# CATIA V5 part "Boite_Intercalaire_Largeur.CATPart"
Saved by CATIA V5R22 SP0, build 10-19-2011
Part number: Boite_Intercalaire_Largeur
Bounding box of the stored display mesh (mm): x -2.5 to 2.5, y -59.5 to 59.5, z -15 to 15
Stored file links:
  U:\S9A\PER\CAO\Assemblage\Reservoir_Boite\Boite\Boite_Intercalaire_Largeur.CATPart
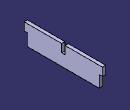
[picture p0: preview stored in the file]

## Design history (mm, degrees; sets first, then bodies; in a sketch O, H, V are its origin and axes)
Body1 (main body)
  Sketch1 on yz-plane, origin (0, 0, 0), H (0, 1, 0), V (0, 0, 1)
    line L1 (-59.5, 15) -> (59.5, 15)
    line L2 (59.5, 15) -> (59.5, -15)
    line L3 (59.5, -15) -> (-59.5, -15)
    line L4 (-59.5, -15) -> (-59.5, 15)
    distance L2 L4 = 119
    distance L1 L3 = 30
    horizontal: L1 H, L3 H
    vertical: L2 V, L4 V
    symmetry: L2 L4 V, L3 L1 H
  Pad1: profile Sketch1, direction (1, 0, 0), length 2.5, mirrored extent
  Sketch2 on yz-plane, origin (0, 0, 0), H (0, 1, 0), V (0, 0, 1)
    line L1 (-2.5, 15) -> (2.5, 15)
    line L2 (2.5, 15) -> (2.5, 3)
    line L3 (2.5, 3) -> (-2.5, 3)
    line L4 (-2.5, 3) -> (-2.5, 15)
    reference projected line E1 (59.5, 15) -> (-59.5, 15) from edge [face of Pad1 from Sketch1.L1 | end face of Pad1]
    distance L2 L4 = 5
    distance L3 L1 = 12
    horizontal: L1 H, L3 H
    vertical: L2 V, L4 V
    coincidence: L1 E1
    symmetry: L2 L4 V
  Pocket1: profile Sketch2, direction (-1, 0, 0), length 5, mirrored extent
  Sketch3 on yz-plane, origin (0, 0, 0), H (0, 1, 0), V (0, 0, 1)
    line L1 (54.5, 3) -> (59.5, 3)
    line L2 (59.5, 3) -> (59.5, -15)
    line L3 (59.5, -15) -> (54.5, -15)
    line L4 (54.5, -15) -> (54.5, 3)
    reference projected line E1 (-59.5, -15) -> (59.5, -15) from edge [face of Pad1 from Sketch1.L3 | end face of Pad1]
    reference projected line E2 (59.5, -15) -> (59.5, 15) from edge [face of Pad1 from Sketch1.L2 | end face of Pad1]
    distance L1 L3 = 18
    distance L4 L2 = 5
    horizontal: L1 H, L3 H
    vertical: L2 V, L4 V
    coincidence: L3 E1, L2 E2
  Pocket2: profile Sketch3, direction (-1, 0, 0), length 5, mirrored extent
  Mirror1: of Pocket2, about zx-plane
